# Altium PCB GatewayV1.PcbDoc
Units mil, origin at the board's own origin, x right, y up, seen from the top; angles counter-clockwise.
Board outline 2120.03 x 2800.03 mil, 2 copper layers (Top Layer, Bottom Layer); 53 components, 42 nets, 229 pads, 121 vias.
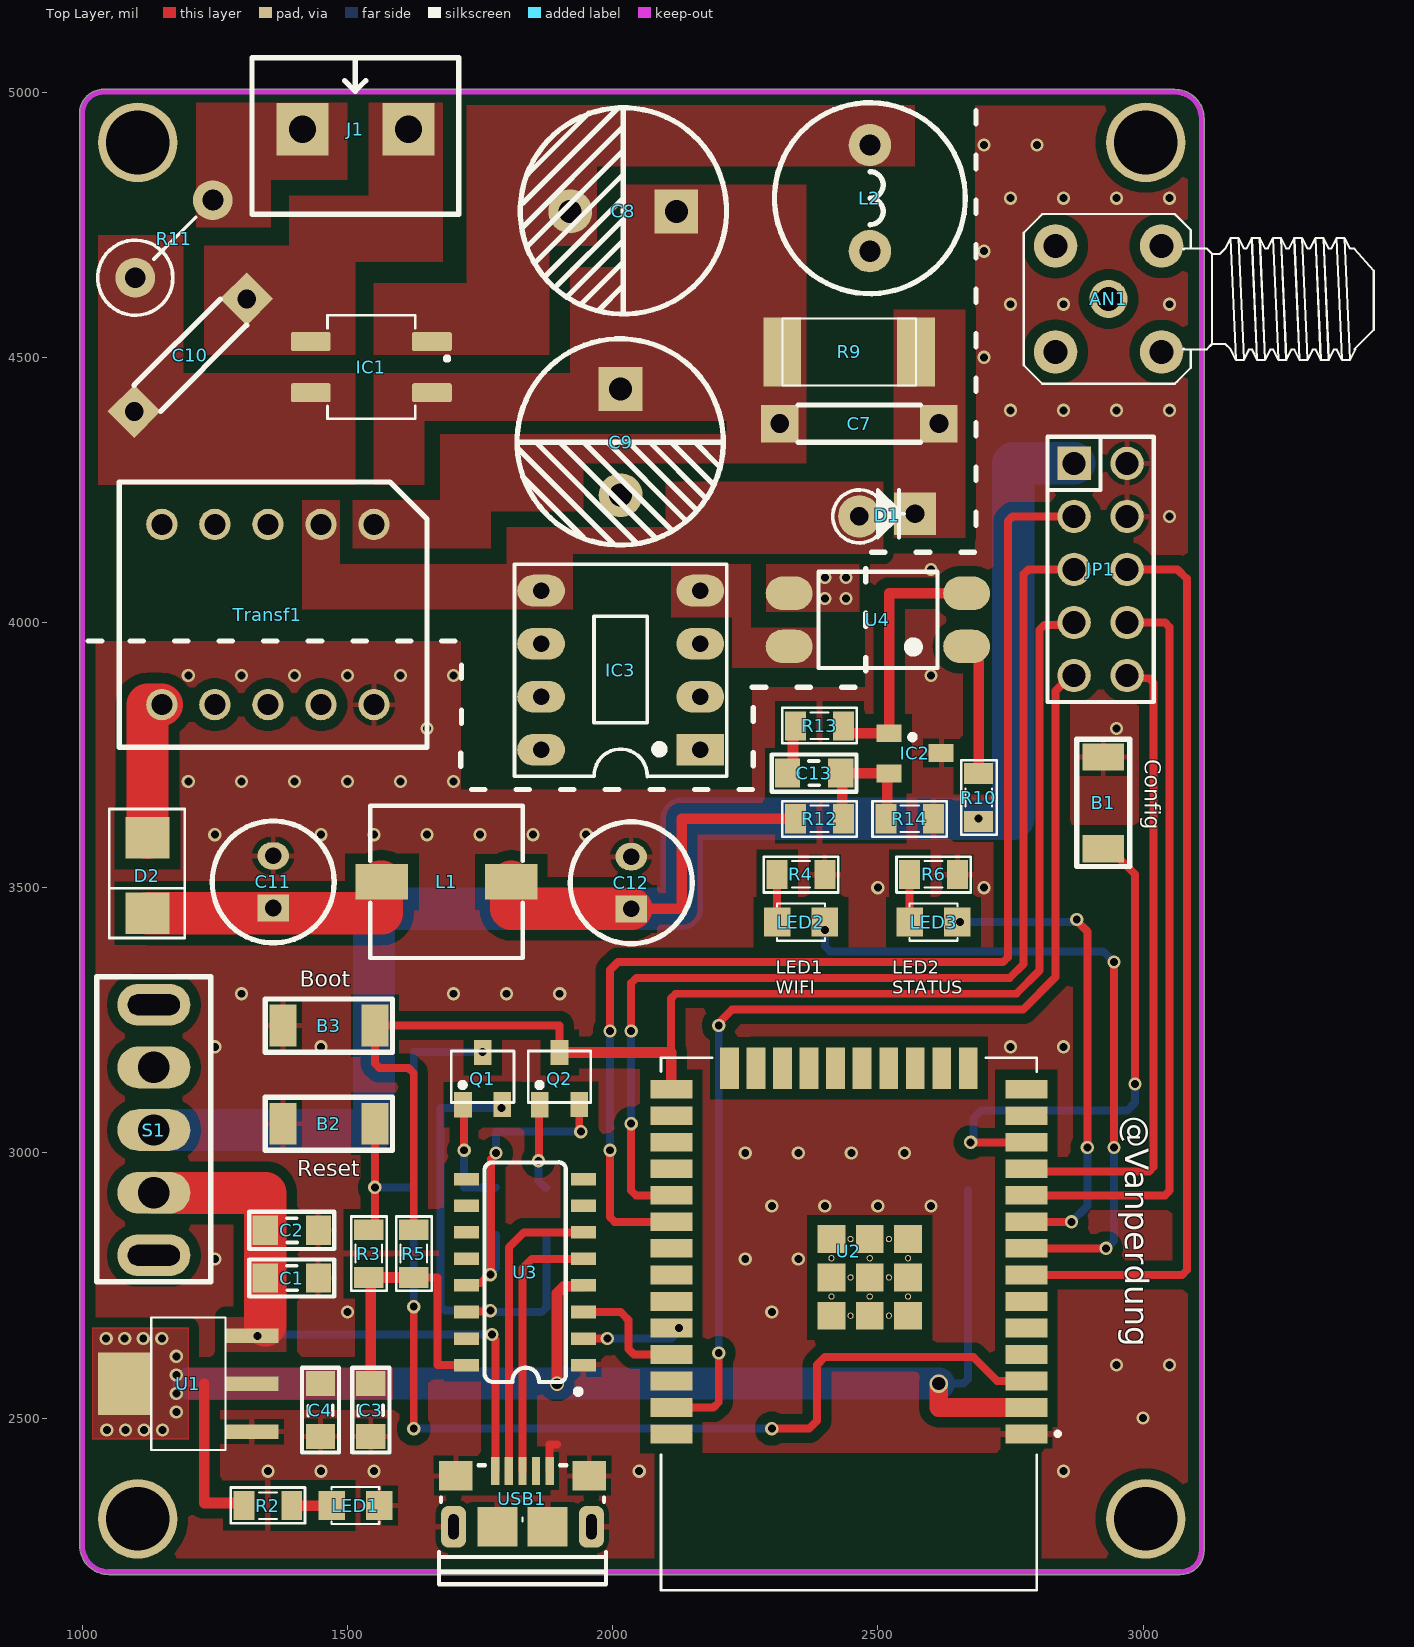
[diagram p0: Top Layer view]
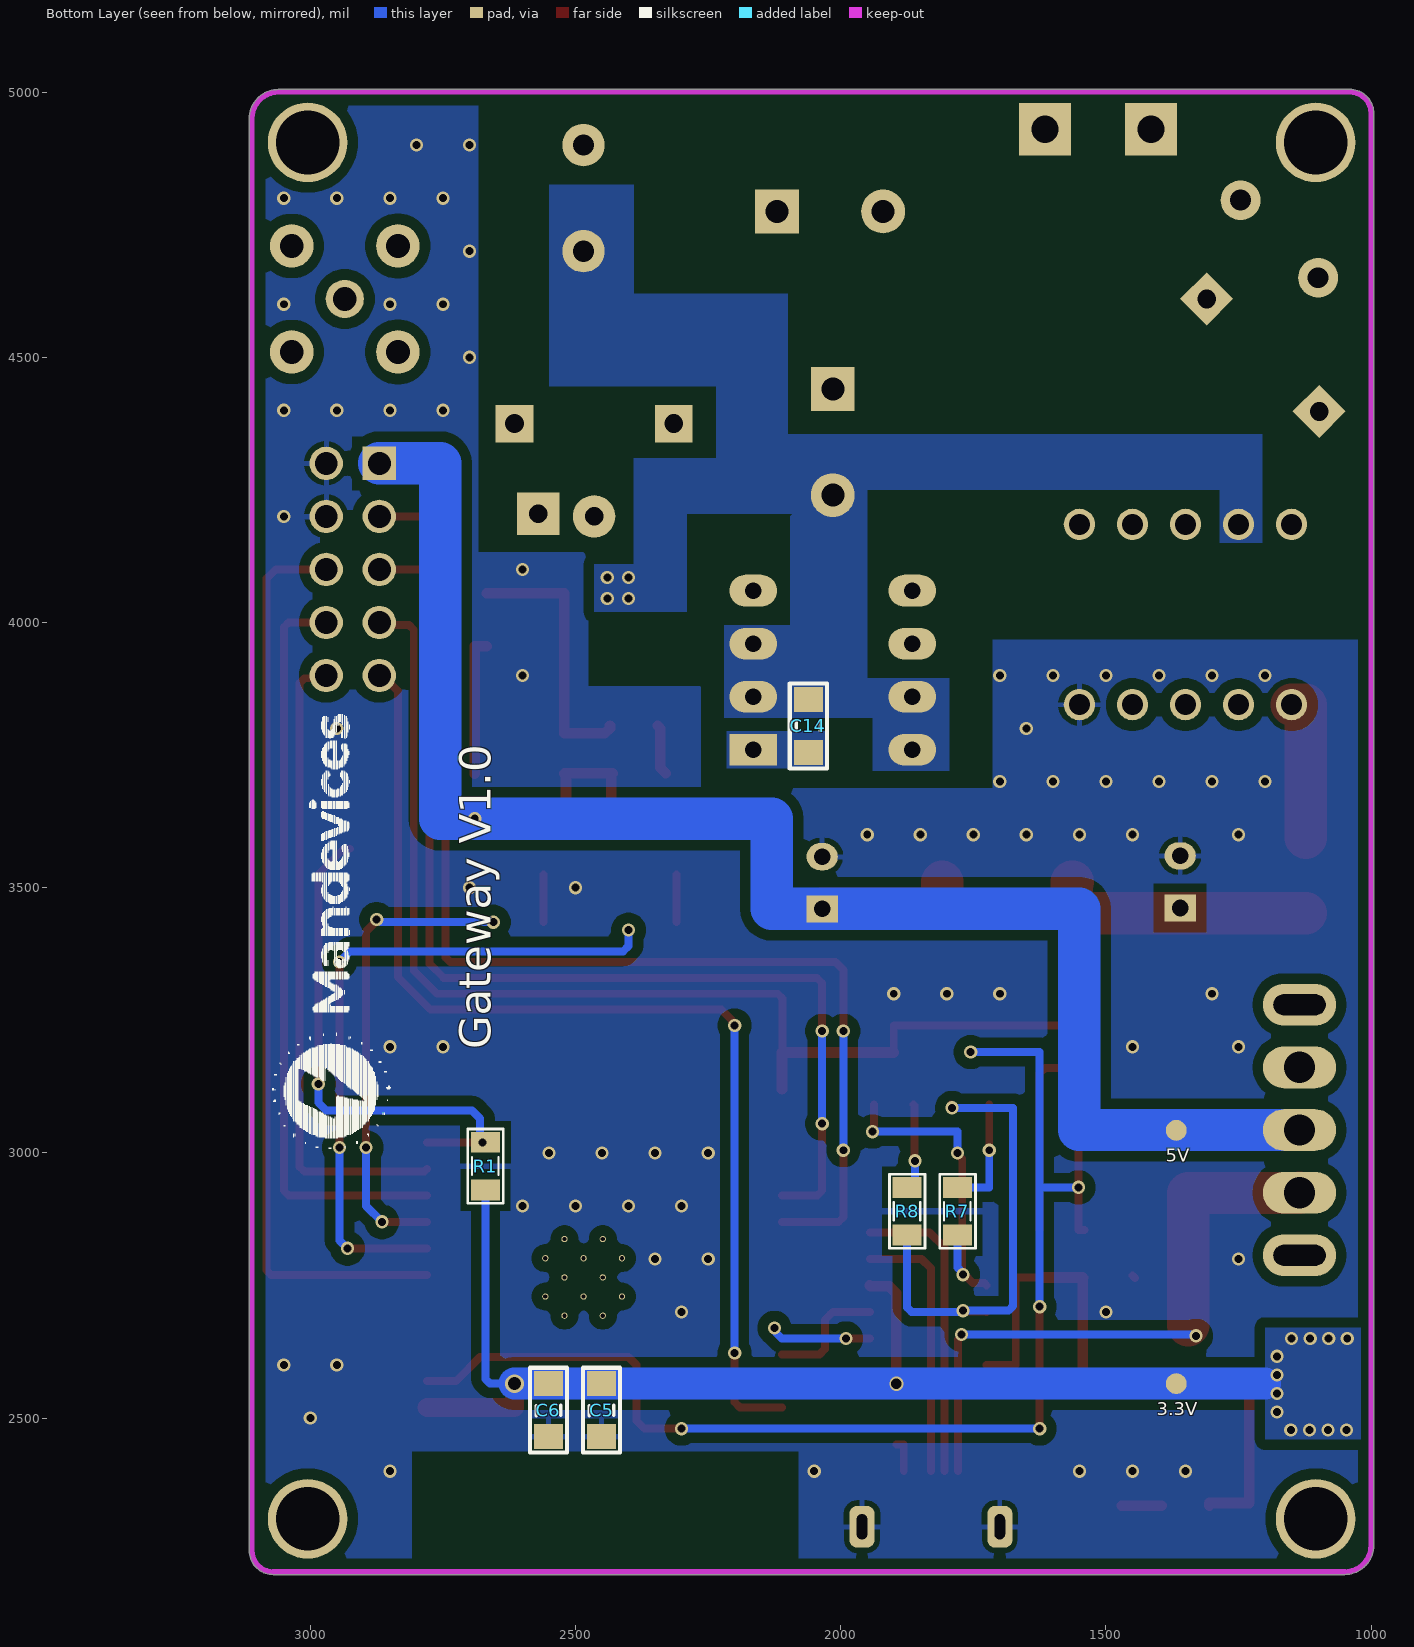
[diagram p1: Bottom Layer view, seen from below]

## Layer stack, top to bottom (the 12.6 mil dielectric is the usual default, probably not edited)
Top Solder: solder mask 0.4, Solder Resist, Dk 3.5
Top Layer: signal copper 1.4
Dielectric 1: dielectric 12.6, FR-4, Dk 4.8
Bottom Layer: signal copper 1.4
Bottom Solder: solder mask 0.4, Solder Resist, Dk 3.5

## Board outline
994.99,2260 994.99,4960 cw(c1040,4960) 1040,5005.02 3060,5005.02 cw(c3060,4950) 3115.01,4950 3115.01,2250 cw(c3070,2250) 3070,2204.99 1050,2204.99 cw(c1050,2260)

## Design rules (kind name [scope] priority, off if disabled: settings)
Clearance [All] p1: gap=15 ignorepadtopadclearanceinfootprint=TRUE
PolygonConnect [All] p1: thpad.connectstyle=Relief thpad.reliefconductorwidth=10 thpad.reliefentries=4 thpad.polygonreliefangle="90 Angle" thpad.airgapwidth=10 smdpad.connectstyle=Relief smdpad.reliefconductorwidth=10 smdpad.reliefentries=4 smdpad.polygonreliefangle="90 Angle" smdpad.airgapwidth=10 via.connectstyle=Direct via.reliefconductorwidth=10 via.reliefentries=4 via.polygonreliefangle="90 Angle" via.airgapwidth=10
RoutingVias [All] p1: holewidth=28 width=50 viastyle="Through Hole" minholewidth=10 minwidth=10 maxholewidth=90 maxwidth=100
SolderMaskExpansion [All] p1: expansion=4 istentingtop=FALSE
Width [All] p1: maxlimit=100 minlimit=10 preferedwidth=10
30 further rules are at their usual default settings.

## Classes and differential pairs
component class Power: C7 C8 C9 C10 C11 C12 C13 C14 D1 D2 IC1 IC2 IC3 J1 L1 L2 R9 R10 R11 R12 R13 R14 S1 Transf1 U4
component class ESP32: AN1 B1 B2 B3 C1 C2 C3 C4 C5 C6 JP1 LED1 LED2 LED3 Q1 Q2 R1 R2 R3 R4 R5 R6 R7 R8 U1 U2 U3 USB1

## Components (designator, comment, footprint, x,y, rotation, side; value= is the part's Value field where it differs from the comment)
AN1 "ANTENA" "DE ANTEN SMA CONG" 2935,4610 r90 top
B1 "Button 3x4x2.5" "Button 3x4x2.5" 2925,3660 r270 top
B2 "Button 3x4x2.5" "Button 3x4x2.5" 1465,3055 r0 top
B3 "Button 3x4x2.5" "Button 3x4x2.5" 1465,3240 r0 top
C1 "10uF" CAP_0805 1395,2765 r0 top value=33p
C2 "100nF" CAP_0805 1395,2855 r0 top value=33p
C3 "10uF" CAP_0805 1545,2515 r270 top value=33p
C4 "100nF" CAP_0805 1450,2515 r270 top value=33p
C5 "100nF" CAP_0805 2450,2515 r270 bottom value=33p
C6 "10uF" CAP_0805 2550,2515 r270 bottom value=33p
C7 "1nF/400V" 103/2KV 2315,4375 r0 top
C8 "10uF/400V" C10mm 2019.65,4772.56 r180 top
C9 "10uF/400V" C10mm 2017.44,4339.65 r270 top
C10 "20D471K" 103/2KV 1310,4610 r225 top
C11 "680uF/16V" C8mm 1360,3510.79 r90 top
C12 "470uF/16V" C8mm 2035,3509.21 r90 top
C13 "100nF" CAP_0805 2380,3715 r180 top value=33p
C14 "100nF" CAP_0805 2060,3805 r270 bottom value=33p
D1 "1N4937" DIO-1AN 2520,4205 r180 top value=1N5007
D2 "SS14" DO-214AC(SMA) 1120,3545 r90 top value=1N5007
IC1 "MB6S" MB6S 1550,4470 r180 top
IC2 "TL431" TL431_SOT 2580,3750 r270 top
IC3 "TNY264" DIP8 2015,3905 r90 top
J1 "AC-IN" KF2-5.08 1515,4930 r0 top
JP1 "JP 2x5 2.54" "JP 2x5 DT" 2920,4100 r270 top
L1 "22uH" L_SMD 1675,3505 r90 top value="150 mH"
L2 "L-DIP-1" Inductor 2485,4800 r270 top value="150 mH"
LED1 "LED" LED-0805-Red 1470,2335 r0 top value="LED 3 ly Single Colour"
LED2 "LED" LED-0805-Red 2400,3435 r180 top value="LED 3 ly Single Colour"
LED3 "LED" LED-0805-Red 2650,3435 r180 top value="LED 3 ly Single Colour"
Q1 "C1815" SOT23D 1755,3140 r0 top
Q2 "C1815" SOT23D 1900,3140 r0 top
R1 "10k" RES-SMD-0805 2670,2975 r90 bottom
R2 "1k" RES-SMD-0805 1350,2335 r180 top
R3 "10k" RES-SMD-0805 1540,2810 r90 top
R4 "1k" RES-SMD-0805 2355,3525 r0 top
R5 "10k" RES-SMD-0805 1625,2810 r90 top
R6 "1k" RES-SMD-0805 2605,3525 r0 top
R7 "10k" RES-SMD-0805 1780,2890 r90 bottom
R8 "10k" RES-SMD-0805 1875,2890 r90 bottom
R9 "82k" RES-SMD-2512 2445.98,4505 r0 top
R10 "200R" RES-SMD-0805 2690,3670 r90 top
R11 "2R/2W" RES-1WW 1145.96,4695.96 r45 top
R12 "10k" RES-SMD-0805 2390,3630 r0 top
R13 "3.3k" RES-SMD-0805 2390,3805 r180 top
R14 "10k" RES-SMD-0805 2560,3630 r0 top
S1 "Switch" Switch 1135,2806.89 r90 top
Transf1 "Transformer EE12.7" "Transformer EE12.7" 1350,4015 r180 top
U1 "LM1117-ADJ" LM1117-SOP 1270,2565 r90 top
U2 "ESP32-WROOM-32" MODULE_ESP32-WROOM-32 2445.35,2677.09 r180 top
U3 "CH340C" SO016 1835,2775 r90 top
U4 "OPTO PC817 SMD" SOP4 2500,4005 r180 top value=PC817
USB1 "USB Micro 5p DIP" "USB Micro 5p DIP" 1830,2295 r0 top

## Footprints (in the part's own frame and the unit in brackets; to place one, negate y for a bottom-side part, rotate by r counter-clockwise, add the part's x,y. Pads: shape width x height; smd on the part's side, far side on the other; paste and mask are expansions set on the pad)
103/2KV [mm]
  rect 1.8x1.8 hole 0.9: 1(0,0) 2(7.62,0)
  silkscreen extent 0.89,-0.89 6.73,0.89, body extent -0.19,-1.2 7.81,1.19, height 9.03
"Button 3x4x2.5" [mm]
  rect 1.3x2 smd: 1(-2.2,0) 2(2.2,0)
  silkscreen extent -3.05,-1.27 3.05,1.27, body extent -2.45,-1.45 2.45,1.45, height 2
C8mm [mm]
  rect 1.3x1.5 hole 0.8: 1(-1.25,0)
  oval 1.3x1.5 hole 0.8: 2(1.25,0)
  silkscreen extent -2.92,-2.92 2.92,2.92, body extent -3.15,-3.15 3.16,3.15, height 11.51
C10mm [mm]
  rect 2.1x2.1 hole 1.1: 1(-2.549,-0.062)
  round 2.1 hole 1.1: 2(2.531,-0.062)
  silkscreen extent -4.96,-5.02 4.92,4.85, body extent -5.01,-5.06 4.96,4.94, height 20.01
CAP_0805 [mm]
  rect 1.2x1.4 smd: 1(-1.27,-0.025) 2(1.27,-0.025)
  silkscreen extent -2.03,-0.91 2.03,0.86, body extent -1.01,-0.66 1.01,0.61, height 0.61
"DE ANTEN SMA CONG" [mil]
  round 72 hole 45: 1(0,0)
  round 82 hole 45: 2(-100,-100) 3(100,-100) 4(100,100) 5(-100,100)
  silkscreen extent -160,-500 160,160, body extent -136,-457 139,137, height 394
DIO-1AN [mil] "Diode 1A, W 100mil, L 150mil"
  round 80 hole 35: 1(55,5)
  rect 80x80 hole 35: 2(-50,0)
  silkscreen extent -30,-45 105,55, body extent -64,-50 104,55, height 252
DIP8 [mil] "DIP, 8-Leads, Row Spacing 7.62mm, Pitch 2.54mm, Body 9.91x6.73mm"
  rect 60x90 hole 31: 1(-145,-150)
  oval 60x90 hole 31: 2(-45,-150) 3(55,-150) 4(155,-150) 5(155,150) 6(55,150) 7(-45,150) 8(-145,150)
  silkscreen extent -195,-200 205,200, body extent -213,-153 213,153, height 177
DO-214AC(SMA) [mm] "DO-214AC Diode Smallest Size"
  rect 2x2.1 smd: 1(1.245,-0.076) 2(-2.367,-0.076)
  silkscreen extent -3.56,-1.86 2.62,1.76, body extent -3.13,-1.38 2.07,1.22, height 2.4
Inductor [mil]
  round 80 hole 40: 1(-100,0) 2(100,0)
  silkscreen extent -180,-180 180,180, body extent -171,-171 171,171, height 394
"JP 2x5 DT" [mm] "10 pins, dual pin, straight, gold plating"
  rect 1.6x1.6 hole 1.1: 1(-5.08,-1.27)
  round 1.6 hole 1.1: 2(-2.54,-1.27) 3(0,-1.27) 4(2.54,-1.27) 5(5.08,-1.27) 6(5.08,1.27) 7(2.54,1.27) 8(0,1.27) 9(-2.54,1.27) 10(-5.08,1.27)
  silkscreen extent -6.35,-2.54 6.35,2.54, body extent -6.35,-2.54 6.35,2.54, height 8.55
KF2-5.08 [mm]
  rect 2.5x2.5 hole 1.3: 1(-2.54,0) 2(2.54,0)
  silkscreen extent -4.95,-4.08 4.95,3.43, body extent -5,-4.07 5,3.43, height 10
L_SMD [mm]
  rect 1.7x2.5 smd: 1(0.15,2.8) 2(0.15,-3.4)
  silkscreen extent -3.5,-3.95 3.8,3.35, body extent -3.5,-3.95 3.8,3.35, height 4.05
LED-0805-Red [mil]
  rect 50x55 smd: 1(0,0) 2(90,0)
  silkscreen extent 0,-35 90,35, body extent 5,-25 85,25, height 43
LM1117-SOP [mm]
  rect 0.7x2.54 smd: 1(-2.3,-1.27) 2(0,-1.27) 3(2.3,-1.27)
  rect 3x2.54 smd: 2(0,4.826)
  silkscreen extent -3.18,0 3.17,3.56, body extent -3.25,-1.78 3.25,5.18, height 1.68
MB6S [mm]
  rrect23% 1.91x0.91 smd: 1(-2.774,0.935) 2(-2.774,-1.515) 3(3.026,-1.515) 4(3.026,0.935)
  silkscreen extent -3.6,-2.77 2.23,2.19, body extent -3.15,-2.61 3.55,2.11, height 2.7
MODULE_ESP32-WROOM-32 [mm]
  rect 2x0.9 smd: 1(-8.5,5.26) 2(-8.5,3.99) 3(-8.5,2.72) 4(-8.5,1.45) 5(-8.5,0.18) 6(-8.5,-1.09) 7(-8.5,-2.36) 8(-8.5,-3.63) 9(-8.5,-4.9) 10(-8.5,-6.17) 11(-8.5,-7.44) 12(-8.5,-8.71) 13(-8.5,-9.98) 14(-8.5,-11.25) 25(8.5,-11.25) 26(8.5,-9.98) 27(8.5,-8.71) 28(8.5,-7.44) 29(8.5,-6.17) 30(8.5,-4.9) 31(8.5,-3.63) 32(8.5,-2.36) 33(8.5,-1.09) 34(8.5,0.18) 35(8.5,1.45) 36(8.5,2.72) 37(8.5,3.99) 38(8.5,5.26)
  rect 0.9x2 smd: 15(-5.715,-12.25) 16(-4.445,-12.25) 17(-3.175,-12.25) 18(-1.905,-12.25) 19(-0.635,-12.25) 20(0.635,-12.25) 21(1.905,-12.25) 22(3.175,-12.25) 23(4.445,-12.25) 24(5.715,-12.25)
  rect 1.33x1.33 smd: 39_1(-2.835,-0.405) 39_2(-1,-0.405) 39_3(0.835,-0.405) 39_4(-2.835,-2.24) 39_5(-1,-2.24) 39_6(0.835,-2.24) 39_7(-2.835,-4.075) 39_8(-1,-4.075) 39_9(0.835,-4.075)
  round 0.3 hole 0.2: 39_10(-1.917,-0.405) 39_11(-0.082,-0.405) 39_12(-2.835,-1.322) 39_13(-1,-1.322) 39_14(0.835,-1.322) 39_15(-1.917,-2.24) 39_16(-0.082,-2.24) 39_17(-2.835,-3.157) 39_18(-1,-3.157) 39_19(0.835,-3.157) 39_20(-1.917,-4.075) 39_21(-0.082,-4.075)
  silkscreen extent -10.1,-12.75 9,12.75, body extent -9.02,-12.75 8.98,12.75, height 3.2
RES-1WW [mm]
  round 1.905 hole 1: 1(-1.651,0) 2(3.6,0)
  silkscreen extent -3.45,-1.8 2.45,1.8
RES-SMD-0805 [mil]
  rect 39.37x55 smd: 1(-45,0) 2(45,0)
  silkscreen extent -70,-34 70,33, body extent -39,-25 39,25, height 31
RES-SMD-2512 [mm] "Chip Capacitor, Body 3.2x2.5mm, IPC Medium Density"
  rect 1.8x3.3 smd: 1(-3.2,0.127) 2(3.2,0.127)
  silkscreen extent -3.2,-1.47 3.2,1.73, body extent -3.2,-1.47 3.2,1.73, height 0.6
SO016 [mm]
  rect 0.6x1.2 smd: 1(-4.445,-2.8) 2(-3.175,-2.8) 3(-1.905,-2.8) 4(-0.635,-2.8) 5(0.635,-2.8) 6(1.905,-2.8) 7(3.175,-2.8) 8(4.445,-2.8) 9(4.445,2.8) 10(3.175,2.8) 11(1.905,2.8) 12(0.635,2.8) 13(-0.635,2.8) 14(-1.905,2.8) 15(-3.175,2.8) 16(-4.445,2.8)
  silkscreen extent -5.84,-2.67 5.26,1.95, body extent -4.99,-3.13 4.99,3.1, height 1.58
SOP4 [mm]
  oval 2.25x1.6 smd: 1(-4.25,1.27) 2(-4.25,-1.27) 3(4.25,-1.27) 4(4.25,1.27)
  silkscreen extent -2.85,-2.3 2.85,2.3, body extent -4.67,-2.29 4.93,2.31, height 3.6
SOT23D [mm] "SOT 23C - 1-3-2 - BCE"
  rect 0.85x1.2 smd: 1(-0.95,-1.25) 2(0.94,-1.245) 3(0,1.25)
  silkscreen extent -1.5,-1.14 1.5,1.32, body extent -1.5,-1.17 1.5,1.33, height 1.06
Switch [mm]
  oval 2x3.5 hole 1.5: 1(3,0) 2(6,0) 3(9,0)
  oval 2x3.5 hole 1 slot 2.5 at 90 deg: 4(0,0) 5(12,0)
  silkscreen extent -1.27,-2.73 13.34,2.73, body extent -0.5,-2.85 12.5,9.35, height 2.6
TL431_SOT [mm]
  rect 0.85x1.2 smd: 1(0.885,-1.5) 2(-0.095,1) 3(-1.04,-1.495)
  silkscreen extent -0.98,-0.5 -0.74,-0.25, body extent -1.57,-1.58 1.43,0.92, height 1.06
"Transformer EE12.7" [mm]
  round 1.5 hole 1: 1(-5.08,-4.318) 2(-2.54,-4.318) 3(0,-4.318) 4(2.54,-4.318) 5(5.08,-4.318) 6(5.08,4.318) 7(2.54,4.318) 8(0,4.318) 9(-2.54,4.318) 10(-5.08,4.318)
  silkscreen extent -7.62,-6.35 7.11,6.35
"USB Micro 5p DIP" [mm]
  rect 0.4x1.35 smd mask+0.05: 1(-1.3,2.675) 2(-0.65,2.675) 3(0,2.675) 4(0.65,2.675) 5(1.3,2.675)
  rrect60% 1.2x2 hole 0.5 slot 1.2 at 90 deg: 5(-3.3,0) 5(3.3,0)
  rect 1.6x1.4 smd: 5(-3.2,2.45) 5(3.2,2.45)
  rect 1.9x1.9 smd paste-10: 5(-1.2,0) 5(1.2,0)
  silkscreen extent -4,-2.75 4,2.95, body extent -3.93,-2.76 3.93,2.9, height 2.85

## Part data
AN1: library part "ANTEN SMA CONG", "Generic Antenna"
C1 C2 C3 C4 C5 C6 C13 C14: library part CapSMD, "Capacitor"
C7: library part Cap2KV, "CAP CERAMIC"
C8 C9 C11 C12: library part "Cap Pol", "Polarized Capacitor (Axial)"
C10: library part Cap2KV, "Varistor"
D1: library part "Diode SMD", "Diode Schottky / 1N4937"
D2: library part "Diode SMD", "Diode Schottky / 1N5819"
IC2: "Programmable Shunt Regulator"
IC3: "Enhanced, Energy Efficient, Low Power Off-line Switcher"
J1: library part KF2, Manufacturer="Würth Elektronik eiSos GmbH", partNo=691103110002
JP1: library part "JP 2x5 2.54 Duc Thang", "Cắm"
L1: library part Inductor, "CD73R 22uH 1.23A 7345"
L2: "Inductor"
LED1 LED2 LED3: "LED Single colour Green and Red"
Q1 Q2: library part 2SC1815, "NPN 600mW, ECB"
R1 R2 R3 R4 R5 R6 R7 R8 R9 R10 R11 R12 R13 R14: library part "Resistor - SMD", "Resistor", Manufacturer="Generic Components"
Transf1: library part "Tranformer EE16"
U1: "800mA Low-Dropout Linear Regulator"
U2: "Bluetooth, WiFi Transceiver Module 2.4GHz ~ 2.5GHz Surface Mount", Package="Module Espressif Systems"
U3: "USB to serial chip CH340", Package=Package
U4: "Single Opto"
USB1: "USB Type B"

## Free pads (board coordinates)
  round 150 hole 120: 0(1104.55,2310) 0(1104.55,4905) 0(3005,2310) 0(3005,4905)
  round 39.37 smd far side: 1(1367.5,2565) 1(1367.5,3042.5)

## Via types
v1: diameter 25, hole 15, Top Layer to Bottom Layer, tented both sides, 119 vias
v2: diameter 27, hole 20, Top Layer to Bottom Layer, tented both sides, 1 vias
v3: diameter 35, hole 25, Top Layer to Bottom Layer, tented both sides, 1 vias

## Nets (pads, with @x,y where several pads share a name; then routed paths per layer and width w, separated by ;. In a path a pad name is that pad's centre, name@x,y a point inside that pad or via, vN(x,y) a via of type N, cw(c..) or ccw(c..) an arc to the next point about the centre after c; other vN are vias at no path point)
+3.3V: C3.1 C4.1 C5.1 C6.1 pad.1@1367.5,2565 R1.1 R2.2 R3.1 R5.1 U1.2 U2.2 U3.4 U3.16 | length 3121.1
  Top Layer w15: R3.1 R3.1@1544,2765 ; R5.1 1670,2765 1670,2600 U3.16
  Top Layer w20: 1230,2565 1230,2340 1305,2340 R2.2 ; C3.1 1544,2765 R5.1 ; v2(1895,2565) 1895,2735 1908.19,2748.19 1943.43,2748.19 U3.4
  Top Layer w35: v3(2615,2565) 2615,2520 U2.2
  Bottom Layer w15: v3(2615,2565) 2661.21,2565 2670,2573.79 R1.1
  Bottom Layer w60: 1200,2565 v2(1895,2565) C6.1 v3(2615,2565)
  other v1: 1046.4,2477.71 1081.4,2477.71 1116.4,2477.71 1151.4,2477.71 1177.29,2511.4 1177.29,2546.4 1177.29,2581.4 1177.29,2616.4 1045,2650 1080,2650 1115,2650 1150,2650
+5: C1.1 C2.1 S1.1 U1.3 USB1.1 | length 1163
  Top Layer w15: v1(1772.5,2657.5) 1772.5,2654.79 1778.82,2648.48 USB1.1
  Top Layer w80: S1.1 1135.63,2924.37 1345,2924.37 C2.1 C1.1 1345,2675
  Bottom Layer w15: v1(1330,2655) 1331.91,2656.91 1338.98,2656.91 1339.57,2657.5 v1(1772.5,2657.5)
+5_sw: C12.1 JP1.1 L1.2 pad.1@1367.5,3042.5 R10.1 R12.1 S1.2 | length 3756.8
  Top Layer w20: C12.1 2130,3460 2130,3630 R12.1 R12.1@2345,3622.19
  Top Layer w80: L1.2 1808.86,3460 C12.1
  Bottom Layer w80: S1.2 1550,3043.11 1550,3460 C12.1 2130,3460 2130,3630 v1(2690,3630) 2755,3630 2755,4300 JP1.1
CH340_RXD: U2.35 U3.3 | length 230.8
  Top Layer w15: U3.3 2015,2700 2019.99,2695.01 2030,2685 2030,2630 2040,2620 U2.35
CH340_TXD: U2.34 U3.2 | length 191.7
  Top Layer w15: U3.2 v1(1990,2650)
  Bottom Layer w15: v1(1990,2650) 2111.21,2650 2123.09,2661.87 2123.09,2668.09 v1(2125,2670)
D_N: U3.6 USB1.2 | length 574.1
  Top Layer w15: USB1.2 1804.41,2821.91 1832.5,2850 U3.6
D_P: U3.5 USB1.3 | length 504.7
  Top Layer w15: USB1.3 1830,2782.5 1847.5,2800 U3.5
DTR: Q2.2 R7.1 U3.13 | length 619.2
  Top Layer w15: U3.13 1729.07,2754.31 1750.55,2754.31 1766.7,2770.46 v1(1769.41,2770.46) ; v1@1768.06,2771.81 1770.89,2774.64 1770.89,2988.18 1780,2997.29 v1(1780,3000) ; Q2.2 1937,3040 v1(1940,3040)
  Bottom Layer w15: v1(1769.41,2770.46) 1769.41,2773.17 1780,2783.76 R7.1 ; v1(1780,3000) 1780,3040 v1(1940,3040)
EN: B2.2 Q1.3 R3.2 U2.3 | length 2416.9
  Top Layer w15: R3.2 1551.61,2855 v1(1551.61,2935) B2.2 ; v1(1625,2480) v1(1625,2710) ; Q1.3 v1(1755,3190) ; v1(2300,2480) 2370,2480 2385,2495 2385,2600 2400,2615 2680,2615 2725,2570 U2.3
  Bottom Layer w15: v1(1551.61,2935) 1625,2935 ; v1(1625,2480) v1(2300,2480) ; v1(1625,2710) 1625,2935 ; v1(1755,3190) 1625,3190 1625,2935
GND: B1.1 B2.1 B3.1 C1.2 C2.2 C3.2 C4.2 C5.2 C6.2 C11.2 C12.2 IC2.2 JP1.9 JP1.10 LED1.2 R4.2 R6.2 R14.2 Transf1.10 U1.1 U2.1 U3.1 USB1.5 | length 70.6
  Top Layer w15: C1.2 C1.2@1450,2769 ; USB1.5@1881.18,2400.32 1881.18,2450 1895,2450
  other v1: 1350,2400 1450,2400 1550,2400 2050,2400 2850,2400 3000,2500 2950,2600 3050,2600 1500,2700 2300,2700 1250,2800 2250,2800 2350,2800 2300,2900 2400,2900 2500,2900 2600,2900 2250,3000 2350,3000 2450,3000 2550,3000 1250,3200 1450,3200 2750,3200 2850,3200 1300,3300 1700,3300 1800,3300 1900,3300 2500,3500 2700,3500 1250,3600 1450,3600 1550,3600 1650,3600 1750,3600 1850,3600 1950,3600 1200,3700 1300,3700 1400,3700 1500,3700 1600,3700 1700,3700 1650,3800 2950,3800 1200,3900 1300,3900 1400,3900 1500,3900 1600,3900 1700,3900 2600,3900 2600,4100 3050,4200 2750,4400 2850,4400 2950,4400 3050,4400 2700,4500 2750,4600 2850,4600 3050,4600 2700,4700 2750,4800 2850,4800 2950,4800 3050,4800 2700,4900 2800,4900
GND_IN: C9.2 C14.1 IC3.2 IC3.3 IC3.7 IC3.8 L2.2 Transf1.4 U4.3
  other v1: 2400,4045 2440,4045 2400,4085 2440,4085
IO0: B3.2 JP1.4 Q2.3 R5.2 U2.25 | length 2658.3
  Top Layer w15: R5.2 1625,3150 1615,3160 1560.4,3160 1551.61,3168.79 B3.2 1900,3240 Q2.3 ; 2110,3189.21 2110,3291.21 2118.79,3300 2761.07,3300 2805,3343.93 2805,3986.21 2813.79,3995 2865,3995 JP1.4
  Top Layer w20: Q2.3 2110.71,3189.21 U2.25
IO5: JP1.3 U2.29 | length 2059.1
  Top Layer w15: v1(2035,3055) 2035,2928.79 2043.79,2920 U2.29 ; v1(2035,3230) 2035,3320 2045,3330 2748.64,3330 2775,3356.36 2775,4091.21 2783.79,4100 JP1.3
  Bottom Layer w15: v1(2035,3055) v1(2035,3230)
IO18: JP1.2 U2.30 | length 2296.5
  Top Layer w15: v1(1995,3005) 1995,2878.79 2003.79,2870 U2.30 ; v1(1995,3230) 1995,3345 2010,3360 2736.21,3360 2745,3368.79 2745,4191.21 2753.79,4200 JP1.2
  Bottom Layer w15: v1(1995,3005) v1(1995,3230)
IO23: JP1.5 U2.37 | length 2065.8
  Top Layer w15: U2.37 2190,2520 2200,2530 v1(2200,2622.5) ; v1(2200,3240) 2200,3242.71 2205,3247.71 2205,3250 2225,3270 2773.49,3270 2835,3331.51 2835,3871.06 2863.94,3900 JP1.5
  Bottom Layer w15: v1(2200,2622.5) v1(2200,3240)
IO25: JP1.7 U2.10 | length 1419.7
  Top Layer w15: U2.10 3041.21,2920 3050,2928.79 3050,3991.21 3041.21,4000 JP1.7
IO26: JP1.6 U2.11 | length 1213.8
  Top Layer w15: U2.11 2785,2965 3011.21,2965 3020,2973.79 3020,3886.06 3011.21,3894.85 2975.15,3894.85 JP1.6
IO27: B1.2 R1.2 U2.12 | length 981.4
  Top Layer w15: v1(2675,3020) U2.12 ; B1.2 2936.91,3573.39 2985,3525.3 v1(2985,3130)
  Bottom Layer w15: v1(2675,3020) 2677.82,3020 2680,3022.18 2680,3065 2695,3080 2970,3080 2985,3095 v1(2985,3130)
IO32: LED2.1 U2.8 | length 1283.6
  Top Layer w15: U2.8 v1(2930,2820) ; v1(2945,3010) v1(2945,3360)
  Bottom Layer w15: v1(2400,3420) 2400,3390 2410,3380 2924.97,3380 v1(2945,3360) ; v1(2930,2820) 2945,2835 v1(2945,3010)
IO33: LED3.1 U2.9 | length 897.8
  Top Layer w15: U2.9 v1(2865,2870) ; v1(2875,3440) 2875,3437.29 2895,3417.29 v1(2895,3010)
  Bottom Layer w15: v1(2655,3435) 2867.29,3435 2872.29,3440 v1(2875,3440) ; v1(2865,2870) 2895,2900 v1(2895,3010)
IO35: JP1.8 U2.7 | length 1729.6
  Top Layer w15: U2.7 3073.71,2770 3082.5,2778.79 3082.5,4082.5 3065,4100 JP1.8
NetC7_1: C7.1 C8.1 C9.1 IC1.1 R9.1 Transf1.1
NetC7_2: C7.2 D1.2 R9.2
NetC8_2: C8.2 IC1.2 L2.1
NetC10_1: C10.1 IC1.3 J1.2
NetC10_2: C10.2 IC1.4 R11.1
NetC11_1: C11.1 D2.2 L1.1 | length 503.6
  Top Layer w80: D2.2 1564.76,3451.8 L1.1 L1.1@1562.09,3510.91
NetC13_1: C13.1 IC2.1 R12.2 R14.1 | length 261.4
  Top Layer w20: C13.1 C13.1@2430.43,3715.57 ; R12.2 2432.5,3632.5 2432.5,3713.5 C13.1@2430.43,3715.57 ; R14.1@2515,3635 2517.97,3637.97 2517.97,3712.17 IC2.1 2520.51,3715.57 C13.1@2430.43,3715.57
NetC13_2: C13.2 R13.2 | length 95.2
  Top Layer w20: C13.2 2340,3726 2340,3800 R13.2
NetC14_2: C14.2 IC3.1
NetD1_1: D1.1 IC3.5 Transf1.2
NetD2_1: D2.1 Transf1.6 | length 278
  Top Layer w80: D2.1 1123,3845 Transf1.6
NetIC2_3: IC2.3 R13.1 U4.2 | length 504.8
  Top Layer w20: R13.1 2435,3800.62 2444.69,3790.94 IC2.3 2521.16,4055 U4.2
NetIC3_4: IC3.4 U4.4
NetJ1_1: J1.1 R11.2
NetLED1_1: LED1.1 R2.1 | length 75
  Top Layer w20: R2.1 LED1.1
NetLED2_2: LED2.2 R4.1 | length 90
  Top Layer w15: LED2.2 R4.1
NetLED3_2: LED3.2 R6.1 | length 90
  Top Layer w15: LED3.2 R6.1
NetQ1_1: Q1.1 R7.2 | length 215.8
  Top Layer w15: v1(1720,3005) Q1.1@1720,3090.79
  Bottom Layer w15: v1(1720,3005) 1720,2935 R7.2
NetQ2_1: Q2.1 R8.2 | length 164.7
  Top Layer w15: v1(1860,2985) 1861.3,2986.3 1861.3,3089.49 Q2.1
  Bottom Layer w15: v1(1860,2985) 1860,2947.18 1872.19,2935 R8.2
NetR10_2: R10.2 U4.1 | length 262.7
  Top Layer w20: U4.1 2690,3955 R10.2
RST: Q1.2 R8.1 U3.14 | length 882.1
  Top Layer w15: U3.14 1726.01,2701.25 1768.16,2701.25 v1(1769.41,2702.5) ; v1(1790,3085) 1792,3087 Q1.2
  Bottom Layer w15: v1(1769.41,2702.5) 1683.79,2702.5 1675,2711.29 1675,3085 v1(1790,3085) ; v1@1772.5,2700 1773.09,2700.59 1776.91,2700.59 1777.5,2700 1866.21,2700 1875,2708.79 R8.1
pads on no net: AN1.1 AN1.2 AN1.3 AN1.4 AN1.5 IC3.6 S1.3 S1.4 S1.5 Transf1.3 Transf1.5 Transf1.7 Transf1.8 Transf1.9 U2.4 U2.5 U2.6 U2.13 U2.14 U2.15 U2.16 U2.17 U2.18 U2.19 U2.20 U2.21 U2.22 U2.23 U2.24 U2.26 U2.27 U2.28 U2.31 U2.32 U2.33 U2.36 U2.38 U2.39_1 U2.39_2 U2.39_3 U2.39_4 U2.39_5 U2.39_6 U2.39_7 U2.39_8 U2.39_9 U2.39_10 U2.39_11 U2.39_12 U2.39_13 U2.39_14 U2.39_15 U2.39_16 U2.39_17 U2.39_18 U2.39_19 U2.39_20 U2.39_21 U3.7 U3.8 U3.9 U3.10 U3.11 U3.12 U3.15 USB1.4

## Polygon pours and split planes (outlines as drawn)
GND on Top Layer "100" (solid, pour order 37): 1713.54,3964.97 1713.54,3684.97 2263.54,3684.97 2263.54,3874.97 2261.04,3877.47 2476.04,3877.47 2476.04,4129.97 2478.54,4132.47 2481.04,4129.97 2683.54,4129.97 2683.54,4994.97 3061.04,4994.97 cw(c3061.04,4952.47) 3103.54,4952.47 3103.54,2247.47 cw(c3071.04,2247.47) 3071.04,2214.97 2808.54,2214.97 2808.54,2434.97 2078.54,2434.97 2078.54,2214.97 1051.04,2214.97 cw(c1051.04,2262.47) 1003.54,2262.47 1003.54,3964.97
no net on Top Layer "100" (solid, pour order 35): 1020,2670 1200,2670 1200,2460 1020,2460
+3.3V on Top Layer "100" (solid, pour order 34): 1020,2670 1020,2460 1200,2460 1200,2670
+3.3V on Top Layer "100" (solid, pour order 33): 1585,2595 1585,2535 1165,2535 1165,2595
+5 on Top Layer "100" (solid, pour order 31): 1270,2690 1270,2625 1385,2625 1385,2690
NetC7_1 on Top Layer "100" (solid, pour order 25): 2365,4355 2365,4300 1770,4300 1770,4140 1510,4140 1510,4230 1675,4230 1675,4355
NetC7_1 on Top Layer "100" (solid, pour order 29): 1770,4300 1945,4300 1945,4210 1770,4210
NetC7_1 on Top Layer "100" (solid, pour order 26): 1550,4380 1550,4260 1645,4260 1645,4380
NetC7_1 on Top Layer "100" (solid, pour order 6): 1550,4470 1550,4380 2080,4380 2080,4550 1920,4550 1920,4470
NetC10_2 on Top Layer "100" (solid, pour order 3): 1515,4470 1515,4260 1030,4260 1030,4470
NetD1_1 on Top Layer "100" (solid, pour order 24): 1800,4025 1415,4025 1415,4230 1485,4230 1485,4110 1800,4110
NetIC3_4 on Top Layer "100" (solid, pour order 22): 2110,4110 2260,4110 2260,3990 2390,3990 2390,3910 2385,3915 2225,3915 2225,4010 2110,4010
GND_IN on Top Layer "100" (solid, pour order 19): 2290,4110 2290,4020 2465,4020 2465,4110
NetD1_1 on Top Layer "100" (solid, pour order 17): 2510,4265 2510,4130 1925,4130 1925,4025 1800,4025 1800,4180 2100,4180 2100,4265
NetC7_2 on Top Layer "100" (solid, pour order 12): 2530,4590 2530,4160 2665,4160 2665,4590
NetC7_1 on Top Layer "100" (solid, pour order 10): 2215,4335 2365,4335 2365,4825 2210,4825
NetC8_2 on Top Layer "100" (solid, pour order 9): 1970,4975 2570,4975 2570,4860 1970,4860
NetC7_1 on Top Layer "100" (solid, pour order 8): 2020,4825 2210,4825 2215,4820 2215,4380 1920,4380 1920,4670 2020,4670
NetJ1_1 on Top Layer "100" (solid, pour order 7): 1500,4980 1500,4835 1355,4835 1355,4745 1215,4745 1215,4980
NetC10_2 on Top Layer "100" (solid, pour order 1): 1030,4730 1030,4335 1190,4335 1190,4730
NetC8_2 on Top Layer "100" (solid, pour order 5): 1550,4505 1880,4505 1880,4710 1970,4710 1970,4975 1725,4975 1725,4640 1550,4640
NetC10_1 on Top Layer "100" (solid, pour order 4): 1540,4980 1680,4980 1680,4680 1390,4680 1390,4805 1540,4805
NetC10_1 on Top Layer "100" (solid, pour order 2): 1230,4710 1230,4505 1515,4505 1515,4710
GND on Bottom Layer "100" (solid, pour order 36): 1713.75,3967.5 1713.75,3687.5 2263.75,3687.5 2263.75,3877.5 2261.25,3880 2476.25,3880 2476.25,4132.5 2478.75,4135 2481.25,4132.5 2683.75,4132.5 2683.75,4997.5 3061.25,4997.5 cw(c3061.25,4955) 3103.75,4955 3103.75,2250 cw(c3071.25,2250) 3071.25,2217.5 2808.75,2217.5 2808.75,2437.5 2078.75,2437.5 2078.75,2217.5 1051.25,2217.5 cw(c1051.25,2265) 1003.75,2265 1003.75,3967.5
+3.3V on Bottom Layer "100" (solid, pour order 32): 1020,2670 1020,2460 1200,2460 1200,2670
NetC14_2 on Bottom Layer "100" (solid, pour order 30): 2030,3795 2030,3725 2215,3725 2215,3795
GND_IN on Bottom Layer "100" (solid, pour order 27): 1950,4355 1205,4355 1205,4150 1285,4150 1285,4250 1950,4250
GND_IN on Bottom Layer "100" (solid, pour order 21): 2235,4310 2290,4310 2290,4205 2235,4205
GND_IN on Bottom Layer "100" (solid, pour order 20): 2390,4110 2465,4110 2465,4020 2390,4020
GND_IN on Bottom Layer "100" (solid, pour order 18): 2290,4310 2390,4310 2390,4020 2290,4020
GND_IN on Bottom Layer "100" (solid, pour order 16): 1950,3995 1950,4205 2090,4205 2095,4200 2095,3995
GND_IN on Bottom Layer "100" (solid, pour order 15): 1795,3895 1795,3720 1940,3720 1940,3820 2220,3820 2220,3995 1950,3995 1950,3895
GND_IN on Bottom Layer "100" (solid, pour order 14): 2390,4445 2235,4445 2235,4205 1950,4205 1950,4355 2100,4355 2100,4620 2390,4620
GND_IN on Bottom Layer "100" (solid, pour order 13): 2390,4825 2390,4445 2550,4445 2550,4825

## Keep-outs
Keep-Out Layer:
  lines w10: 3110,4940 3110,2250 ; 3110,2250 cw(c3070,2250) 3070,2210 3010,2210 1050,2210 cw(c1050,2260) 1000,2260 1000,4960 cw(c1040,4960) 1040,5000 3010,5000 3060,5000 cw(c3060,4950) 3110,4950 3110,2250

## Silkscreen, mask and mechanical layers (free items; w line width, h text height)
Top Overlay:
  lines w10: 1011.56,3965 1036.56,3965 ; 1090,3965 1115,3965 ; 1174.06,3965 1199.06,3965 ; 1258.12,3965 1283.12,3965 ; 1342.19,3965 1367.19,3965 ; 1426.25,3965 1451.25,3965 ; 1510.31,3965 1535.31,3965 ; 1594.38,3965 1619.38,3965 ; 1677.5,3965 1702.5,3965 ; 1713.77,3728.4 1713.77,3753.4 ; 1715,3810 1715,3835 ; 1715,3895 1715,3920 ; 1734.06,3685 1759.06,3685 ; 1818.12,3685 1843.12,3685 ; 1902.19,3685 1927.19,3685 ; 1986.25,3685 2011.25,3685 ; 2070.31,3685 2095.31,3685 ; 2154.38,3685 2179.38,3685 ; 2238.44,3685 2263.44,3685 ; 2263.38,3877.81 2288.38,3877.81 ; 2265,3730 2265,3755 ; 2265,3814.06 2265,3839.06 ; 2347.44,3877.81 2372.44,3877.81 ; 2431.51,3877.81 2456.51,3877.81 ; 2477.19,3908.38 2477.19,3933.38 ; 2477.19,3992.44 2477.19,4017.44 ; 2477.19,4076.51 2477.19,4101.51 ; 2488.49,4132.19 2513.49,4132.19 ; 2572.56,4132.19 2597.56,4132.19 ; 2656.62,4132.19 2681.62,4132.19 ; 2685,4183.44 2685,4208.44 ; 2685,4267.5 2685,4292.5 ; 2685,4351.56 2685,4376.56 ; 2685,4435.62 2685,4460.62 ; 2685,4519.69 2685,4544.69 ; 2685,4603.44 2685,4628.44 ; 2685,4687.5 2685,4712.5 ; 2685,4771.56 2685,4796.56 ; 2685,4855.62 2685,4880.62 ; 2685,4939.69 2685,4964.69
  text "Config" at 3003,3742 h30 r270
  text "Boot" at 1410.5,3313 h30
  text "LED1 / WIFI" at 2307.5,3300 h25
  text "LED2 / STATUS" at 2527.5,3300 h25
  text "@Vanperdung" at 2966.61,3069.91 h45 r270
  text "Reset" at 1405.5,2955.5 h30
Bottom Overlay:
  drawing of 654 lines, arcs and shapes, not listed
  text "Gateway V1.0" at 2659.99,3195 h60 r270
  text "5V" at 1387,2983 h25
  text "3.3V" at 1404.5,2505.5 h25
